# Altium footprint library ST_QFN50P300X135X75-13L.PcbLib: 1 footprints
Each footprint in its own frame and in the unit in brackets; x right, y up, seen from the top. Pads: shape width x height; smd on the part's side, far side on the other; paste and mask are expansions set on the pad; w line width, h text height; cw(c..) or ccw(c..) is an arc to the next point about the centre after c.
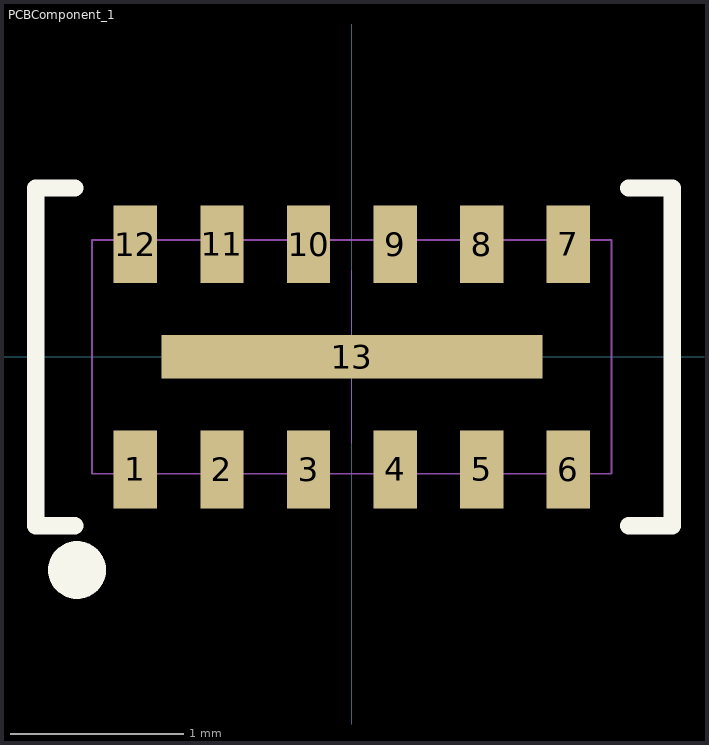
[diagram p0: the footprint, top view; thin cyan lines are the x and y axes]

## PCBComponent_1 [mm]
pads (13):
  rect 0.25x0.45 smd paste-20 mask+0.05: 1(-1.25,-0.65) 2(-0.75,-0.65) 3(-0.25,-0.65) 4(0.25,-0.65) 5(0.75,-0.65) 6(1.25,-0.65) 7(1.25,0.65) 8(0.75,0.65) 9(0.25,0.65) 10(-0.25,0.65) 11(-0.75,0.65) 12(-1.25,0.65)
  rect 2.2x0.25 smd paste-20 mask+0.025: 13(0,0)
Top Overlay:
  circle w0.2: c-1.587,-1.231 r0.067
  lines w0.1: -1.6,-0.975 -1.825,-0.975 -1.825,0.975 -1.6,0.975 ; 1.6,-0.975 1.85,-0.975 1.85,0.975 1.6,0.975
Top Paste:
  rectangle: -1.37,-0.865 -1.13,-0.435
  rectangle: -0.87,-0.865 -0.63,-0.435
  rectangle: -0.37,-0.865 -0.13,-0.435
  rectangle: 0.13,-0.865 0.37,-0.435
  rectangle: 0.63,-0.865 0.87,-0.435
  rectangle: 1.13,-0.865 1.37,-0.435
  rectangle: 1.13,0.435 1.37,0.865
  rectangle: 0.63,0.435 0.87,0.865
  rectangle: 0.13,0.435 0.37,0.865
  rectangle: -0.37,0.435 -0.13,0.865
  rectangle: -0.87,0.435 -0.63,0.865
  rectangle: -1.37,0.435 -1.13,0.865
  rectangle: -0.78,-0.09 0.78,0.09
Top Solder:
  rectangle: -1.15,-0.15 1.15,0.15
Mechanical 15:
  lines w0.001: -0.5,0 0.5,0 ; 0,-0.5 0,0.5
  lines w0.01: -1.5,-0.675 1.5,-0.675 1.5,0.675 -1.5,0.675 -1.5,-0.675
3D body: height 0.75, standoff 0.02, extent -1.5,-0.675 1.5,0.675
3D body: height 0.75, standoff 0.02, extent -2.097,0.783 -2.097,0.783
3D body: height 0.75, standoff 0.02, extent -1.418,0.158 -1.418,0.158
